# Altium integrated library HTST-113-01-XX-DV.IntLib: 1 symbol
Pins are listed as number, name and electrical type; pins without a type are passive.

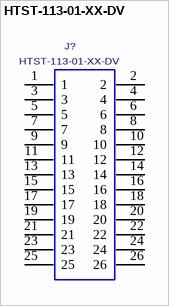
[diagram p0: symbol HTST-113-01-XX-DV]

## HTST-113-01-XX-DV
designator J?
HIGH TEMP TOP SHROUD.; MANUFACTURER: SAMTEC
footprint HTST-113-01-XX-DV
pins: 1, 2, 3, 4, 5, 6, 7, 8, 9, 10, 11, 12, 13, 14, 15, 16, 17, 18, 19, 20, 21, 22, 23, 24, 25, 26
